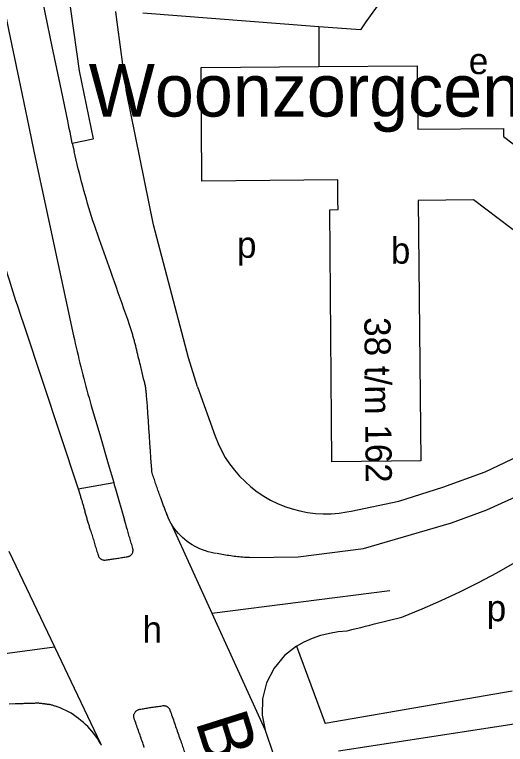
# Model space of a CAD drawing. Extents: x 159045 to 160918, y 380454 to 382516.
# Drawn here: x 160524.1 to 160599, y 381517.5 to 381628.9 of the extents above; entities that cross this region are included whole.
import ezdxf

# ---------------------------------------------------------------- set-up
doc = ezdxf.new("R2010")
doc.units = 0
for name, color, linetype in [('BLT_Basislijn', 7, 'Continuous'), ('BLT_Bebouwing', 7, 'Continuous'), ('BLT_Bebouwing_beschrifting', 7, 'Continuous'), ('BLT_Centroide', 7, 'Continuous'), ('BLT_Huisnummer_reeks', 7, 'Continuous'), ('BLT_Straatnaam_hoofdweg', 7, 'Continuous'), ('BLT_Vlakafsluiter', 7, 'Continuous')]:
    doc.layers.add(name, color=color, linetype=linetype)

msp = doc.modelspace()

# ---------------------------------------------------------------- linework, layer by layer
at = {"layer": 'BLT_Basislijn'}
for p, q in [((160570.57, 381627.06), (160570.57, 381620.97)), ((160532.93, 381609.3), (160536.12, 381609.95)), ((160532.93, 381609.3), (160533.2, 381608.04)), ((160527.13, 381607.83), (160533.12, 381579.91)), ((160525.61, 381581.26), (160533.81, 381556.52)), ((160552.02, 381572.12), (160554.72, 381564.6)), ((160535.82, 381569.23), (160537.11, 381564.82)), ((160537.11, 381564.82), (160538.41, 381560.36)), ((160538.41, 381560.36), (160539.24, 381557.53)), ((160533.81, 381556.52), (160539.24, 381557.53)), ((160596.21, 381553.33), (160602.18, 381556.06)), ((160575.48, 381553.14), (160582.76, 381554.65)), ((160590.8, 381551.34), (160596.21, 381553.33)), ((160577.37, 381547.45), (160590.8, 381551.34)), ((160567.39, 381546.18), (160577.37, 381547.45)), ((160559.98, 381546.05), (160567.39, 381546.18)), ((160554.23, 381537.55), (160581.37, 381541.01)), ((160583.21, 381536.95), (160586.34, 381538.23)), ((160579.05, 381535.92), (160583.21, 381536.95)), ((160501.58, 381528.5), (160530.2, 381532.45)), ((160567.15, 381532.54), (160571.51, 381520.75)), ((160600.05, 381525.67), (160571.51, 381520.75)), ((160602.84, 381521.04), (160573.54, 381516.53)), ((160562.35, 381519.71), (160563.66, 381515.98))]:
    msp.add_line(p, q, dxfattribs=at)
for points in [[(160533.81, 381713.04), (160533.21, 381705.3), (160532.22, 381692.42), (160530.89, 381667.81), (160530.67, 381655.34), (160530.77, 381650.22), (160531.45, 381638.5), (160533.95, 381620.32), (160536.12, 381609.95)], [(160517.12, 381655.67), (160518.65, 381648.35), (160520.18, 381641.03), (160521.71, 381633.72), (160523.24, 381626.4), (160524.77, 381619.09), (160526.3, 381611.77), (160527.13, 381607.83)], [(160532.93, 381609.3), (160532.82, 381609.86), (160532.7, 381610.42), (160532.58, 381610.98), (160532.47, 381611.54), (160532.35, 381612.1), (160532.23, 381612.67), (160531.26, 381617.32), (160529.86, 381624.02), (160528.46, 381630.72), (160527.06, 381637.42), (160525.66, 381644.12), (160524.26, 381650.83), (160523.31, 381655.33), (160523.29, 381655.46), (160523.26, 381655.58), (160523.24, 381655.68)], [(160552.02, 381572.12), (160550.66, 381576.53), (160545.32, 381596.85), (160541.18, 381617.1), (160539.68, 381628.52), (160539.57, 381629.36)], [(160536.5, 381596.15), (160536.29, 381596.8), (160536.08, 381597.45), (160535.87, 381598.1), (160535.67, 381598.76), (160535.47, 381599.42), (160535.27, 381600.07), (160535.08, 381600.73), (160534.89, 381601.39), (160534.7, 381602.05), (160534.52, 381602.71), (160534.34, 381603.37), (160534.17, 381604.04), (160534, 381604.7), (160533.83, 381605.37), (160533.67, 381606.03), (160533.51, 381606.7), (160533.35, 381607.37), (160533.2, 381608.04)], [(160541.68, 381581.55), (160541.39, 381582.37), (160541.1, 381583.19), (160540.81, 381584.01), (160540.52, 381584.83), (160540.23, 381585.65), (160539.94, 381586.47), (160539.65, 381587.29), (160539.36, 381588.11), (160539.07, 381588.93), (160538.8, 381589.7), (160538.54, 381590.41), (160538.29, 381591.13), (160538.03, 381591.85), (160537.78, 381592.56), (160537.52, 381593.28), (160537.27, 381594), (160537.01, 381594.71), (160536.76, 381595.43), (160536.5, 381596.15)], [(160521.2, 381595.14), (160521.4, 381594.48), (160521.6, 381593.82), (160521.8, 381593.16), (160522, 381592.5), (160522.2, 381591.85), (160522.41, 381591.19), (160522.61, 381590.54), (160522.82, 381589.88), (160523.03, 381589.22), (160523.23, 381588.57), (160523.44, 381587.91), (160523.65, 381587.26), (160523.86, 381586.6), (160524.07, 381585.95), (160524.28, 381585.3), (160524.5, 381584.64), (160524.71, 381583.99), (160524.93, 381583.34), (160525.61, 381581.26)], [(160542.52, 381578.67), (160542.48, 381578.82), (160542.44, 381578.97), (160542.4, 381579.13), (160542.36, 381579.28), (160542.32, 381579.43), (160542.28, 381579.58), (160542.23, 381579.74), (160542.19, 381579.89), (160542.15, 381580.04), (160542.1, 381580.19), (160542.06, 381580.34), (160542.01, 381580.49), (160541.97, 381580.64), (160541.92, 381580.79), (160541.87, 381580.95), (160541.82, 381581.1), (160541.78, 381581.25), (160541.73, 381581.4), (160541.68, 381581.55)], [(160533.12, 381579.91), (160533.25, 381579.31), (160533.38, 381578.71), (160533.52, 381578.11), (160533.66, 381577.52), (160533.8, 381576.92), (160533.94, 381576.33), (160534.08, 381575.73), (160534.23, 381575.14), (160534.38, 381574.55), (160534.53, 381573.96), (160534.69, 381573.36), (160534.84, 381572.77), (160535, 381572.18), (160535.16, 381571.59), (160535.32, 381571), (160535.49, 381570.41), (160535.65, 381569.82), (160535.82, 381569.23)], [(160582.76, 381554.65), (160589.49, 381556.78), (160595.93, 381559.12), (160603.14, 381562.54), (160606.33, 381564.51), (160611.27, 381568.24), (160616.38, 381573.28), (160618.83, 381576.15), (160621.53, 381579.86)], [(160543.81, 381573.35), (160543.75, 381573.58), (160543.7, 381573.82), (160543.64, 381574.05), (160543.59, 381574.28), (160543.53, 381574.51), (160543.48, 381574.74), (160543.42, 381574.97), (160543.37, 381575.2), (160543.31, 381575.43), (160543.24, 381575.71), (160543.16, 381576.04), (160543.08, 381576.37), (160543, 381576.7), (160542.92, 381577.03), (160542.84, 381577.35), (160542.76, 381577.68), (160542.68, 381578.01), (160542.6, 381578.34), (160542.52, 381578.67)], [(160586.34, 381538.23), (160589.23, 381539.49), (160592.1, 381540.83), (160594.92, 381542.24), (160597.71, 381543.73), (160600.47, 381545.28), (160603.18, 381546.91), (160605.85, 381548.6), (160608.48, 381550.35), (160611.06, 381552.18), (160613.6, 381554.07), (160616.08, 381556.02), (160618.52, 381558.03), (160620.9, 381560.11), (160623.24, 381562.24), (160625.51, 381564.44), (160627.73, 381566.69), (160629.9, 381568.99), (160632, 381571.35), (160634.04, 381573.77), (160636.02, 381576.23), (160637.69, 381578.4)], [(160544.25, 381570.71), (160544.24, 381570.86), (160544.23, 381571.02), (160544.21, 381571.17), (160544.2, 381571.33), (160544.18, 381571.48), (160544.17, 381571.63), (160544.15, 381571.79), (160544.13, 381571.94), (160544.1, 381572.1), (160544.08, 381572.25), (160544.05, 381572.4), (160544.02, 381572.56), (160544, 381572.71), (160543.96, 381572.86), (160543.81, 381573.35)], [(160545.1, 381558.98), (160545.09, 381559.09), (160545.08, 381559.14), (160545.08, 381559.2), (160545.07, 381559.25), (160545.07, 381559.31), (160545.06, 381559.37), (160545.06, 381559.42), (160545.05, 381559.48), (160545.01, 381560.07), (160544.93, 381561.21), (160544.85, 381562.35), (160544.77, 381563.49), (160544.7, 381564.63), (160544.62, 381565.77), (160544.54, 381566.91), (160544.46, 381568.05), (160544.38, 381569.19), (160544.25, 381570.71)], [(160554.72, 381564.6), (160555.17, 381563.48), (160555.69, 381562.4), (160556.28, 381561.35), (160556.94, 381560.35), (160557.66, 381559.4), (160558.45, 381558.49), (160559.29, 381557.64), (160560.2, 381556.84), (160561.15, 381556.11), (160562.14, 381555.44), (160563.18, 381554.84), (160564.26, 381554.32), (160565.37, 381553.86), (160566.51, 381553.48), (160567.67, 381553.17), (160568.85, 381552.95), (160570.04, 381552.8), (160571.24, 381552.73), (160572.44, 381552.75), (160573.64, 381552.84), (160574.83, 381553.01), (160575.48, 381553.14)], [(160546.42, 381555.15), (160546.35, 381555.35), (160546.28, 381555.56), (160546.21, 381555.76), (160546.14, 381555.96), (160546.07, 381556.16), (160546, 381556.36), (160545.93, 381556.56), (160545.86, 381556.76), (160545.79, 381556.96), (160545.72, 381557.17), (160545.65, 381557.37), (160545.58, 381557.57), (160545.51, 381557.77), (160545.45, 381557.97), (160545.38, 381558.17), (160545.31, 381558.37), (160545.24, 381558.57), (160545.17, 381558.77), (160545.1, 381558.98)], [(160539.24, 381557.53), (160539.34, 381557.17), (160539.53, 381556.53), (160540.91, 381551.76)], [(160533.81, 381556.52), (160534.11, 381555.58), (160534.16, 381555.44), (160534.2, 381555.3), (160534.24, 381555.16), (160534.28, 381555.02), (160534.32, 381554.88), (160534.36, 381554.74), (160534.41, 381554.6), (160534.45, 381554.46), (160534.49, 381554.32), (160534.53, 381554.18), (160534.57, 381554.04), (160534.61, 381553.9), (160534.66, 381553.76), (160534.7, 381553.62), (160534.74, 381553.48), (160534.78, 381553.34), (160534.82, 381553.2), (160534.86, 381553.06)], [(160547.5, 381552.31), (160547.44, 381552.46), (160547.38, 381552.61), (160547.33, 381552.76), (160547.27, 381552.91), (160547.21, 381553.06), (160547.16, 381553.21), (160547.1, 381553.36), (160547.04, 381553.51), (160546.99, 381553.66), (160546.93, 381553.81), (160546.87, 381553.96), (160546.81, 381554.11), (160546.76, 381554.26), (160546.7, 381554.41), (160546.64, 381554.55), (160546.59, 381554.7), (160546.53, 381554.85), (160546.47, 381555), (160546.42, 381555.15)], [(160535.71, 381550.23), (160535.66, 381550.38), (160535.62, 381550.53), (160535.57, 381550.68), (160535.53, 381550.83), (160535.48, 381550.98), (160535.44, 381551.12), (160535.4, 381551.27), (160535.35, 381551.42), (160535.31, 381551.57), (160535.26, 381551.72), (160535.22, 381551.87), (160535.17, 381552.02), (160535.13, 381552.17), (160535.09, 381552.32), (160535.04, 381552.46), (160535, 381552.61), (160534.95, 381552.76), (160534.91, 381552.91), (160534.86, 381553.06)], [(160542.17, 381547.44), (160542.05, 381547.85), (160541.99, 381548.05), (160541.93, 381548.26), (160541.87, 381548.47), (160541.81, 381548.67), (160541.75, 381548.88), (160541.69, 381549.08), (160541.63, 381549.29), (160541.57, 381549.49), (160541.51, 381549.7), (160541.45, 381549.9), (160541.39, 381550.11), (160541.33, 381550.31), (160541.27, 381550.52), (160541.21, 381550.72), (160541.15, 381550.93), (160541.09, 381551.14), (160540.91, 381551.76)], [(160548.03, 381551.19), (160548, 381551.25), (160547.97, 381551.31), (160547.93, 381551.37), (160547.9, 381551.43), (160547.87, 381551.5), (160547.84, 381551.56), (160547.81, 381551.62), (160547.78, 381551.68), (160547.75, 381551.74), (160547.72, 381551.81), (160547.69, 381551.87), (160547.66, 381551.93), (160547.63, 381551.99), (160547.61, 381552.06), (160547.58, 381552.12), (160547.55, 381552.18), (160547.53, 381552.25), (160547.5, 381552.31)], [(160548.07, 381551.13), (160548.03, 381551.19)], [(160554.95, 381546.68), (160554.52, 381546.75), (160554.1, 381546.83), (160553.67, 381546.94), (160553.24, 381547.07), (160552.82, 381547.22), (160552.41, 381547.39), (160552, 381547.58), (160551.6, 381547.79), (160551.21, 381548.02), (160550.83, 381548.27), (160550.46, 381548.53), (160550.1, 381548.81), (160549.76, 381549.1), (160549.44, 381549.41), (160549.13, 381549.74), (160548.84, 381550.07), (160548.56, 381550.41), (160548.3, 381550.77), (160548.07, 381551.13)], [(160535.71, 381550.23), (160535.77, 381550.03), (160535.83, 381549.83), (160535.89, 381549.63), (160535.95, 381549.42), (160536.01, 381549.22), (160536.08, 381549.02), (160536.14, 381548.82), (160536.2, 381548.62), (160536.26, 381548.41), (160536.32, 381548.21), (160536.38, 381548.01), (160536.44, 381547.81), (160536.51, 381547.61), (160536.57, 381547.41), (160536.63, 381547.2), (160536.69, 381547), (160536.75, 381546.8), (160536.81, 381546.6), (160536.88, 381546.4)], [(160541.32, 381546.19), (160541.4, 381546.2), (160541.48, 381546.22), (160541.57, 381546.25), (160541.65, 381546.29), (160541.73, 381546.33), (160541.8, 381546.38), (160541.88, 381546.44), (160541.95, 381546.51), (160542.01, 381546.58), (160542.06, 381546.66), (160542.11, 381546.74), (160542.14, 381546.83), (160542.17, 381546.92), (160542.19, 381547.01), (160542.2, 381547.1), (160542.2, 381547.19), (160542.2, 381547.28), (160542.19, 381547.36), (160542.17, 381547.44)], [(160536.88, 381546.4), (160536.9, 381546.33), (160536.92, 381546.27), (160536.95, 381546.2), (160536.99, 381546.14), (160537.03, 381546.08), (160537.08, 381546.02), (160537.13, 381545.97), (160537.19, 381545.92), (160537.25, 381545.87), (160537.31, 381545.83), (160537.38, 381545.79), (160537.45, 381545.76), (160537.52, 381545.73), (160537.59, 381545.71), (160537.66, 381545.69), (160537.73, 381545.68), (160537.8, 381545.68), (160537.87, 381545.68), (160537.94, 381545.68)], [(160537.94, 381545.68), (160538.11, 381545.71), (160538.29, 381545.73), (160538.46, 381545.76), (160538.64, 381545.78), (160538.81, 381545.81), (160538.99, 381545.83), (160539.16, 381545.86), (160539.33, 381545.88), (160539.51, 381545.91), (160539.69, 381545.93), (160539.87, 381545.96), (160540.05, 381545.99), (160540.23, 381546.02), (160540.41, 381546.05), (160540.6, 381546.08), (160540.78, 381546.11), (160540.96, 381546.14), (160541.14, 381546.16), (160541.32, 381546.19)], [(160559.98, 381546.05), (160559.72, 381546.06), (160559.46, 381546.08), (160559.2, 381546.09), (160558.93, 381546.11), (160558.67, 381546.14), (160558.41, 381546.16), (160558.15, 381546.19), (160557.89, 381546.21), (160557.62, 381546.24), (160557.36, 381546.28), (160557.1, 381546.31), (160556.84, 381546.35), (160556.58, 381546.39), (160556.32, 381546.43), (160556.06, 381546.47), (160555.8, 381546.52), (160555.54, 381546.57), (160555.28, 381546.62), (160555.03, 381546.67)], [(160574.88, 381534.89), (160575.57, 381535.06), (160576.27, 381535.24), (160576.96, 381535.41), (160577.66, 381535.58), (160578.35, 381535.75), (160579.05, 381535.92)], [(160567.15, 381532.54), (160568.34, 381533.19), (160569.58, 381533.75), (160570.87, 381534.2), (160572.19, 381534.54), (160573.53, 381534.77), (160574.88, 381534.89)], [(160567.15, 381532.54), (160565.3, 381531.09), (160563.72, 381529.19), (160562.58, 381526.94), (160561.96, 381524.48), (160561.9, 381522.02), (160562.35, 381519.71)], [(160523.28, 381523.74), (160524.18, 381523.8), (160524.62, 381523.79)], [(160524.62, 381523.79), (160524.78, 381523.79), (160524.94, 381523.8), (160525.1, 381523.8), (160525.26, 381523.81), (160525.42, 381523.81), (160525.58, 381523.82), (160525.75, 381523.82), (160525.91, 381523.83), (160526.07, 381523.83), (160526.23, 381523.83), (160526.39, 381523.84), (160526.55, 381523.84), (160526.71, 381523.85), (160526.87, 381523.85), (160527.03, 381523.86), (160527.19, 381523.86), (160527.35, 381523.87), (160527.51, 381523.87), (160527.67, 381523.88)], [(160527.67, 381523.88), (160527.76, 381523.87), (160527.86, 381523.86), (160527.95, 381523.85), (160528.05, 381523.84), (160528.14, 381523.83), (160528.23, 381523.82), (160528.33, 381523.81), (160528.42, 381523.8), (160528.52, 381523.79), (160528.61, 381523.78), (160528.7, 381523.76), (160528.8, 381523.75), (160528.89, 381523.74), (160528.98, 381523.72), (160529.08, 381523.71), (160529.17, 381523.7), (160529.26, 381523.68), (160529.36, 381523.67), (160529.45, 381523.65)], [(160530.62, 381523.29), (160530.5, 381523.33), (160530.37, 381523.37), (160530.25, 381523.4), (160530.13, 381523.44), (160530, 381523.48), (160529.88, 381523.52), (160529.76, 381523.56), (160529.64, 381523.59), (160529.51, 381523.63), (160529.45, 381523.65)], [(160537.23, 381517.69), (160537, 381518.08), (160536.75, 381518.47), (160536.48, 381518.84), (160536.21, 381519.21), (160535.91, 381519.57), (160535.61, 381519.92), (160535.29, 381520.26), (160534.96, 381520.59), (160534.61, 381520.91), (160534.25, 381521.21), (160533.89, 381521.5), (160533.51, 381521.78), (160533.12, 381522.04), (160532.73, 381522.29), (160532.33, 381522.52), (160531.92, 381522.73), (160531.5, 381522.93), (160531.08, 381523.12), (160530.62, 381523.29)], [(160542.36, 381521.54), (160542.34, 381521.63), (160542.32, 381521.71), (160542.31, 381521.8), (160542.31, 381521.9), (160542.32, 381521.99), (160542.34, 381522.09), (160542.37, 381522.19), (160542.4, 381522.28), (160542.45, 381522.37), (160542.5, 381522.46), (160542.56, 381522.54), (160542.63, 381522.61), (160542.71, 381522.68), (160542.79, 381522.74), (160542.87, 381522.78), (160542.96, 381522.82), (160543.04, 381522.86), (160543.13, 381522.88), (160543.21, 381522.9)], [(160543.21, 381522.9), (160543.4, 381522.93), (160543.59, 381522.96), (160543.77, 381522.99), (160543.96, 381523.03), (160544.15, 381523.06), (160544.34, 381523.09), (160544.52, 381523.12), (160544.71, 381523.16), (160544.9, 381523.19), (160545.09, 381523.22), (160545.28, 381523.25), (160545.47, 381523.27), (160545.66, 381523.3), (160545.85, 381523.32), (160546.04, 381523.35), (160546.23, 381523.38), (160546.42, 381523.4), (160546.62, 381523.43), (160546.81, 381523.46)], [(160546.81, 381523.46), (160546.87, 381523.46), (160546.94, 381523.46), (160547, 381523.45), (160547.07, 381523.44), (160547.14, 381523.43), (160547.21, 381523.41), (160547.28, 381523.38), (160547.34, 381523.35), (160547.4, 381523.31), (160547.46, 381523.27), (160547.52, 381523.23), (160547.57, 381523.18), (160547.62, 381523.13), (160547.67, 381523.08), (160547.71, 381523.02), (160547.75, 381522.96), (160547.78, 381522.9), (160547.8, 381522.84), (160547.83, 381522.78)], [(160547.83, 381522.78), (160547.91, 381522.53), (160548, 381522.29), (160548.09, 381522.04), (160548.17, 381521.79), (160548.26, 381521.54), (160548.35, 381521.29), (160548.43, 381521.05), (160548.52, 381520.8), (160548.61, 381520.55), (160548.69, 381520.3), (160548.78, 381520.05), (160548.87, 381519.81), (160548.95, 381519.56), (160549.04, 381519.31), (160549.13, 381519.06), (160549.21, 381518.81), (160549.3, 381518.57), (160549.39, 381518.32), (160549.48, 381518.07)], [(160543.91, 381517.1), (160543.83, 381517.33), (160543.75, 381517.56), (160543.67, 381517.8), (160543.59, 381518.03), (160543.5, 381518.27), (160543.42, 381518.5), (160543.34, 381518.73), (160543.26, 381518.97), (160543.18, 381519.2), (160543.09, 381519.44), (160543.01, 381519.67), (160542.93, 381519.9), (160542.85, 381520.14), (160542.77, 381520.37), (160542.69, 381520.61), (160542.6, 381520.84), (160542.52, 381521.07), (160542.44, 381521.31), (160542.36, 381521.54)], [(160537.38, 381517.41), (160537.37, 381517.42), (160537.36, 381517.44), (160537.36, 381517.45), (160537.35, 381517.47), (160537.34, 381517.48), (160537.33, 381517.5), (160537.33, 381517.51), (160537.32, 381517.53), (160537.31, 381517.54), (160537.3, 381517.56), (160537.29, 381517.57), (160537.29, 381517.59), (160537.28, 381517.6), (160537.27, 381517.62), (160537.26, 381517.63), (160537.25, 381517.64), (160537.25, 381517.66), (160537.24, 381517.67), (160537.23, 381517.69)], [(160549.48, 381518.07), (160549.55, 381517.86), (160549.62, 381517.66), (160549.69, 381517.45), (160549.76, 381517.24), (160549.83, 381517.04), (160549.9, 381516.83), (160549.97, 381516.63), (160550.04, 381516.42), (160550.11, 381516.21), (160550.18, 381516.01), (160550.25, 381515.8), (160550.32, 381515.59), (160550.39, 381515.39), (160550.47, 381515.18), (160550.54, 381514.97), (160550.61, 381514.77), (160550.68, 381514.56), (160550.75, 381514.35), (160550.82, 381514.15)]]:
    msp.add_lwpolyline(points, dxfattribs=at)
at = {"layer": 'BLT_Bebouwing'}
for p, q in [((160598.72, 381610.31), (160610.54, 381601.37)), ((160594.15, 381600.63), (160585.71, 381600.56)), ((160604.22, 381593.02), (160594.15, 381600.63))]:
    msp.add_line(p, q, dxfattribs=at)
for points in [[(160585.86, 381639.08), (160577.75, 381627.79)], [(160570.57, 381627.06), (160543.68, 381629.1)], [(160577.75, 381627.79), (160576.89, 381626.58), (160570.57, 381627.06)], [(160573.48, 381600.45), (160573.45, 381603.7), (160552.72, 381603.51), (160552.57, 381620.81), (160570.57, 381620.97)], [(160570.57, 381620.97), (160585.56, 381621.09), (160585.65, 381611.4), (160598.73, 381611.52), (160598.72, 381610.31)], [(160585.71, 381600.56), (160586.12, 381560.8), (160572.56, 381560.68), (160572.23, 381599.14), (160573.49, 381599.15), (160573.48, 381600.45)]]:
    msp.add_lwpolyline(points, dxfattribs=at)
at = {"layer": 'BLT_Vlakafsluiter'}
for p, q in [((160548.03, 381551.19), (160554.23, 381537.55)), ((160523.25, 381547.05), (160530.2, 381532.45)), ((160554.23, 381537.55), (160562.35, 381519.71)), ((160530.2, 381532.45), (160537.23, 381517.69))]:
    msp.add_line(p, q, dxfattribs=at)

# ---------------------------------------------------------------- texts
at = {"layer": 'BLT_Bebouwing_beschrifting'}
msp.add_text('Woonzorgcentrum', height=8, dxfattribs=at).set_placement((160535.43, 381613.35))
at = {"layer": 'BLT_Centroide'}
for s, p in [('e', (160593.45, 381619.82)), ('p', (160558.06, 381591.8)), ('b', (160581.55, 381590.91)), ('p', (160596.18, 381536.34)), ('h', (160543.64, 381533.09))]:
    msp.add_text(s, height=4, dxfattribs=at).set_placement(p)
at = {"layer": 'BLT_Huisnummer_reeks'}
msp.add_text('38 t/m 162', height=4, rotation=270.5005, dxfattribs=at).set_placement((160577.49, 381582.73))
at = {"layer": 'BLT_Straatnaam_hoofdweg'}
msp.add_text('BAYEUXLAAN', height=8, rotation=287.502, dxfattribs=at).set_placement((160551.66, 381521.06))

doc.saveas('drawing.dxf')
